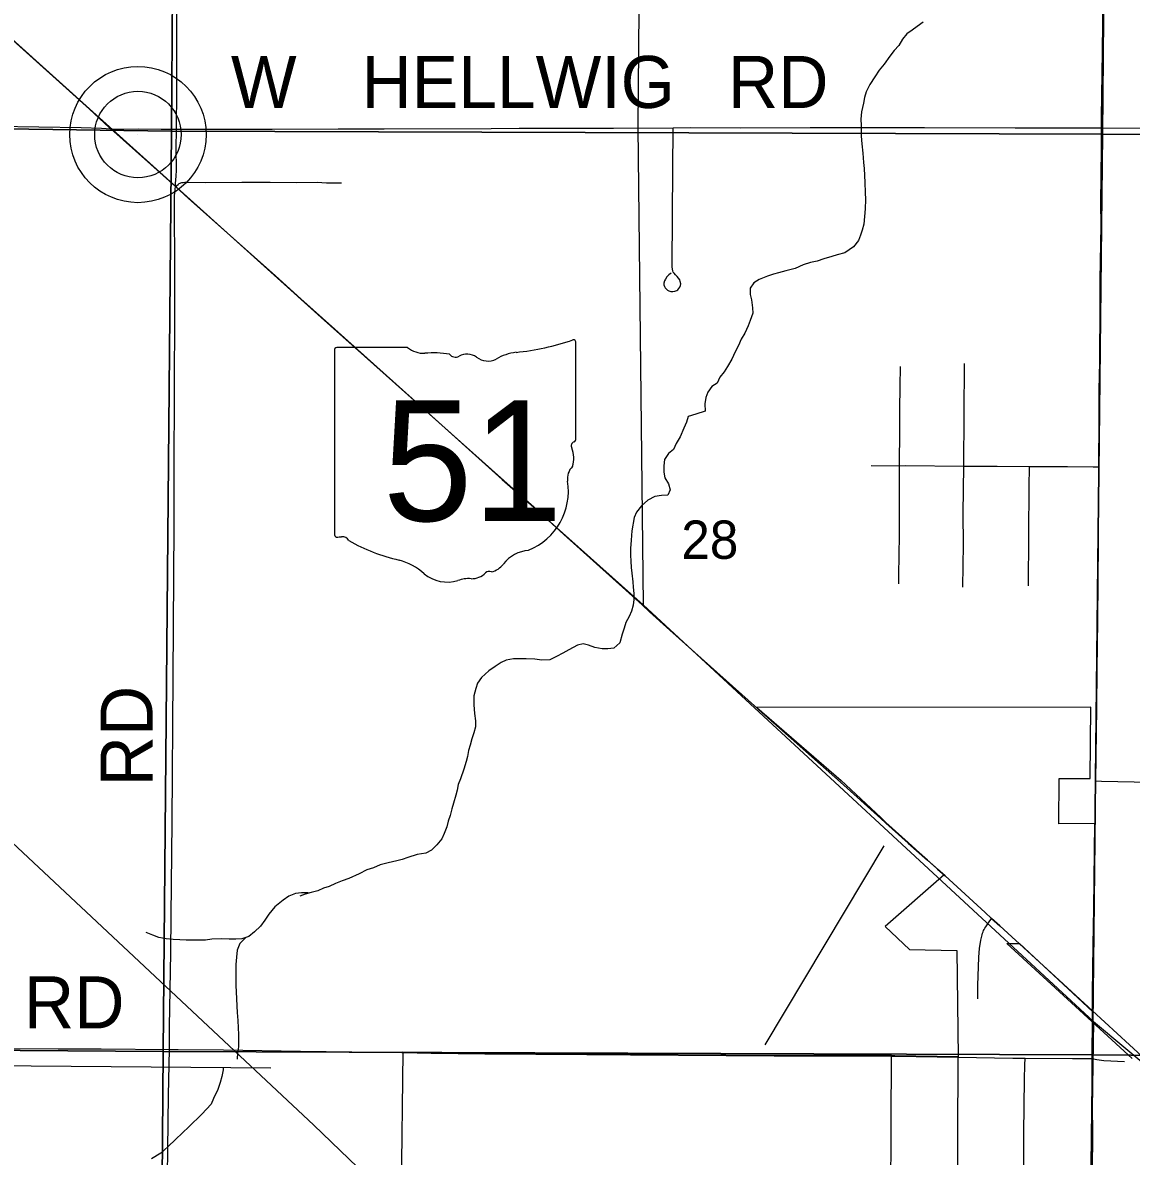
# Model space of a CAD drawing. Extents: x 0 to 34, y 0 to 22.
# Drawn here: x 6.452 to 7.662, y 15.265 to 16.502 of the extents above; entities that cross this region are included whole.
import ezdxf

# ---------------------------------------------------------------- set-up
doc = ezdxf.new("R2010")
doc.units = 0
for name, color, linetype in [('Default', 7, 'Continuous'), ('GM_X_City_Street', 7, 'Continuous'), ('GM_X_County_Road', 7, 'Continuous'), ('GM_X_Minor_River', 7, 'Continuous'), ('GM_X_Rail_Line', 7, 'Continuous'), ('GM_X_Section', 7, 'Continuous'), ('GM_X_Section_Text', 7, 'Continuous'), ('GM_X_State_Location', 7, 'Continuous'), ('GM_X_State_Route', 7, 'Continuous'), ('GM_X_State_Shield', 7, 'Continuous'), ('GM_X_Township_Road', 7, 'Continuous'), ('GM_X_Township_Road_Text', 7, 'Continuous'), ('GM_X_Unincorporated', 7, 'Continuous'), ('GM_X_Unincorporated_Location', 7, 'Continuous')]:
    doc.layers.add(name, color=color, linetype=linetype)

msp = doc.modelspace()

# ---------------------------------------------------------------- linework, layer by layer
at = {"layer": 'Default'}
msp.add_lwpolyline([(7.6625, 15.3715), (7.5256, 15.497), (7.5396, 15.4969), (7.6191, 15.4226), (7.6193, 15.4426), (7.6201, 15.4951), (7.6207, 15.5352), (7.6215, 15.5978), (7.6218, 15.6278), (7.5824, 15.6274), (7.583, 15.6771), (7.6166, 15.6769), (7.6174, 15.7548), (7.2529, 15.7546), (7.3449, 15.6747), (7.3881, 15.6343), (7.3937, 15.629), (7.3936, 15.6289), (7.4179, 15.607), (7.4388, 15.5883), (7.4573, 15.5719), (7.3929, 15.5155), (7.4195, 15.4902), (7.4713, 15.4893), (7.4725, 15.3733), (7.4036, 15.3744), (7.3998, 15.3745), (7.362, 15.3746), (7.2715, 15.3747), (7.1147, 15.3757), (7.067, 15.3762), (6.9559, 15.3769), (6.897, 15.3779), (6.8663, 15.3783), (6.8645, 15.2275)], dxfattribs=at)
at = {"layer": 'GM_X_City_Street'}
for points in [[(7.4941, 15.4366), (7.4942, 15.4509), (7.4951, 15.4821), (7.4959, 15.4914), (7.4973, 15.5005), (7.4987, 15.5065), (7.4992, 15.5081), (7.4998, 15.5098), (7.5003, 15.511), (7.5008, 15.5121), (7.5017, 15.5135), (7.5027, 15.5152), (7.5056, 15.5193), (7.509, 15.5243)], [(7.3978, 15.1171), (7.3978, 15.119), (7.3979, 15.1731), (7.3983, 15.2203), (7.3993, 15.2661), (7.3995, 15.3037), (7.4, 15.3716), (7.4, 15.3739)], [(7.4703, 15.1166), (7.4714, 15.1932), (7.4721, 15.2501), (7.4724, 15.2871), (7.4727, 15.3698), (7.4727, 15.3728)], [(7.4727, 15.3728), (7.5322, 15.3718), (7.5456, 15.3717), (7.5974, 15.3712), (7.6188, 15.3712)], [(7.542, 14.9047), (7.5419, 14.9076), (7.5416, 14.9133), (7.5417, 14.9334), (7.5421, 14.9939), (7.5423, 15.0326), (7.5429, 15.0915), (7.5431, 15.1101), (7.5433, 15.1165), (7.5436, 15.1287), (7.5438, 15.1875), (7.5437, 15.203), (7.5442, 15.2495), (7.5442, 15.2501), (7.5442, 15.265), (7.5443, 15.2898), (7.5449, 15.3486), (7.5454, 15.3641), (7.5456, 15.3717)], [(7.6188, 15.3712), (7.6239, 15.3702), (7.6317, 15.3692), (7.6541, 15.368)]]:
    msp.add_lwpolyline(points, dxfattribs=at)
at = {"layer": 'GM_X_County_Road'}
for p, q in [((7.6227, 15.6745), (7.6239, 15.7541)), ((7.622, 15.6272), (7.6227, 15.6745)), ((7.6192, 15.4095), (7.6193, 15.4233))]:
    msp.add_line(p, q, dxfattribs=at)
for points in [[(7.6291, 16.3875), (7.6291, 16.399), (7.63, 16.4704), (7.6314, 16.5977), (7.6327, 16.694), (7.6332, 16.7499), (7.6341, 16.8182), (7.6347, 16.8648), (7.6351, 16.9176), (7.6358, 16.9672), (7.6359, 16.9859), (7.6362, 17.0194)], [(7.6263, 16.0175), (7.6265, 16.0698), (7.6266, 16.1009), (7.6271, 16.1319), (7.6275, 16.194), (7.6277, 16.222), (7.6285, 16.281), (7.6284, 16.3058), (7.629, 16.3648), (7.6291, 16.3875)], [(7.6239, 15.7541), (7.6242, 15.7956), (7.625, 15.85), (7.6256, 15.935), (7.6263, 16.0175)], [(7.6193, 15.4233), (7.6196, 15.442), (7.6203, 15.4945), (7.6209, 15.5347), (7.6217, 15.5972), (7.622, 15.6272)], [(7.6188, 15.3712), (7.6189, 15.3828), (7.6192, 15.4056), (7.6192, 15.4095)], [(7.6191, 15.2489), (7.6196, 15.2882), (7.6187, 15.3518), (7.6188, 15.3712)]]:
    msp.add_lwpolyline(points, dxfattribs=at)
at = {"layer": 'GM_X_Minor_River'}
for points in [[(7.4344, 16.5029), (7.4279, 16.498), (7.4222, 16.4942), (7.4165, 16.49), (7.412, 16.4843), (7.4078, 16.4775), (7.4029, 16.4718), (7.398, 16.4657), (7.3919, 16.457), (7.3862, 16.4505), (7.3817, 16.4433), (7.3763, 16.435), (7.3722, 16.427), (7.3703, 16.4205), (7.3691, 16.4145), (7.3672, 16.405), (7.3665, 16.397), (7.3668, 16.3902), (7.3668, 16.3784), (7.3676, 16.37), (7.3684, 16.3598), (7.3691, 16.3495), (7.3699, 16.3431), (7.3706, 16.3279), (7.371, 16.3169), (7.3714, 16.3093), (7.371, 16.299), (7.3695, 16.2823), (7.3679, 16.2759), (7.3661, 16.2702), (7.3638, 16.2645), (7.3585, 16.2576), (7.349, 16.2512), (7.3406, 16.2489), (7.3346, 16.247), (7.3259, 16.2444), (7.3187, 16.2421), (7.3115, 16.2406), (7.3035, 16.2379), (7.2948, 16.2338), (7.2845, 16.2315), (7.2766, 16.2292), (7.2709, 16.2277), (7.2644, 16.2254), (7.2553, 16.222), (7.2497, 16.2182), (7.2455, 16.2125), (7.2455, 16.2057), (7.247, 16.1996), (7.2481, 16.1909), (7.2485, 16.1852), (7.2455, 16.1772), (7.2432, 16.1715), (7.2398, 16.1632), (7.2356, 16.1567), (7.233, 16.1499), (7.2292, 16.143), (7.2254, 16.1351)], [(7.2254, 16.1351), (7.2208, 16.1271), (7.217, 16.121), (7.2125, 16.1153), (7.2094, 16.1089), (7.2038, 16.1051), (7.1992, 16.099), (7.1973, 16.0929), (7.1962, 16.0861), (7.1965, 16.0781), (7.1863, 16.0747), (7.178, 16.0724), (7.1761, 16.066), (7.173, 16.0595), (7.1692, 16.05), (7.1647, 16.0428), (7.162, 16.0364), (7.1563, 16.0318), (7.1522, 16.0254), (7.1514, 16.0185), (7.1514, 16.0117), (7.1525, 16.0053), (7.1563, 15.9988), (7.1582, 15.9923), (7.1556, 15.9866), (7.1487, 15.9859), (7.1415, 15.9848), (7.134, 15.981), (7.1271, 15.9749), (7.1214, 15.9677), (7.1188, 15.962), (7.1165, 15.9476), (7.1158, 15.9373), (7.115, 15.9282), (7.115, 15.921), (7.1154, 15.9145), (7.1157, 15.9073), (7.1165, 15.9012), (7.1176, 15.8917), (7.118, 15.886), (7.1184, 15.8792), (7.1184, 15.8724), (7.118, 15.8663), (7.1161, 15.8598), (7.1134, 15.8538), (7.11, 15.8473), (7.1081, 15.8412), (7.1059, 15.8348), (7.1032, 15.8253), (7.0968, 15.8192), (7.0903, 15.8185), (7.0839, 15.8185), (7.0759, 15.82), (7.0691, 15.8227), (7.0634, 15.8242), (7.057, 15.8227), (7.0475, 15.8174), (7.041, 15.814), (7.0342, 15.8102), (7.027, 15.8067), (7.0183, 15.8064), (7.0107, 15.8075), (7.0012, 15.8079), (6.9872, 15.8079), (6.9792, 15.8064), (6.9736, 15.8037), (6.9671, 15.7992), (6.9603, 15.7946), (6.9523, 15.7874), (6.9481, 15.781), (6.9462, 15.7753), (6.944, 15.7673), (6.944, 15.7574), (6.9447, 15.7479), (6.9459, 15.74), (6.9459, 15.7335), (6.944, 15.7271), (6.9417, 15.7202), (6.9398, 15.7134), (6.9383, 15.7077), (6.9371, 15.7012), (6.9356, 15.6956), (6.9329, 15.6872), (6.9295, 15.6766), (6.9269, 15.6705), (6.9257, 15.6644), (6.9242, 15.6587), (6.9219, 15.65), (6.92, 15.6439), (6.9181, 15.6367), (6.9159, 15.6306), (6.9144, 15.6242), (6.9117, 15.617), (6.909, 15.6113), (6.9037, 15.6048), (6.8977, 15.5988), (6.8916, 15.5957), (6.8821, 15.5942), (6.8719, 15.5908), (6.8658, 15.5885), (6.8598, 15.587)], [(7.3916, 15.6037), (7.2615, 15.3863)], [(6.8598, 15.587), (6.8503, 15.5851), (6.8416, 15.5828), (6.8344, 15.5794), (6.8271, 15.5772), (6.8188, 15.573), (6.8074, 15.5677), (6.8002, 15.5654), (6.793, 15.5624), (6.7862, 15.5593), (6.7798, 15.5574), (6.7737, 15.5544), (6.7665, 15.5525), (6.76, 15.5506), (6.754, 15.5487)], [(6.7631, 15.5521), (6.7559, 15.5521), (6.7494, 15.5514), (6.7422, 15.5484), (6.7358, 15.5442), (6.7267, 15.537), (6.7202, 15.529), (6.7157, 15.5222), (6.7111, 15.5157), (6.7047, 15.5097), (6.6982, 15.5047), (6.6907, 15.5021), (6.6842, 15.5017), (6.677, 15.5017), (6.6683, 15.5021), (6.6581, 15.5017), (6.6509, 15.5006), (6.63, 15.5006), (6.6232, 15.501), (6.6156, 15.5014), (6.608, 15.5021), (6.6001, 15.5036), (6.5936, 15.5059), (6.5864, 15.509)], [(6.695, 15.5036), (6.6884, 15.4968), (6.6857, 15.4895), (6.685, 15.4819), (6.6842, 15.474), (6.6842, 15.4512), (6.6849, 15.4368), (6.6853, 15.4284), (6.6857, 15.4216), (6.6865, 15.4128), (6.6868, 15.4049), (6.6872, 15.3977), (6.6872, 15.384), (6.6861, 15.3775), (6.6857, 15.3707)], [(6.7224, 15.3608), (5.1099, 15.3744), (5.1125, 15.1557), (4.6992, 15.1313)], [(6.6705, 15.3612), (6.6705, 15.3589), (6.669, 15.3517), (6.6671, 15.3453), (6.6644, 15.3373), (6.6599, 15.3278), (6.6572, 15.3214), (6.647, 15.3107), (6.633, 15.2967), (6.6261, 15.2902), (6.6182, 15.283), (6.6102, 15.2751), (6.6022, 15.2679), (6.592, 15.2618)]]:
    msp.add_lwpolyline(points, dxfattribs=at)
at = {"layer": 'GM_X_Rail_Line'}
msp.add_line((7.1287, 15.8668), (7.6203, 15.4116), dxfattribs=at)
for points in [[(5.1871, 17.6191), (5.4266, 17.4037), (5.6472, 17.1998), (6.051, 16.8348), (6.7774, 16.1806), (7.1287, 15.8668)], [(7.1325, 17.6042), (7.1272, 17.4005), (7.1287, 17.0765), (7.1229, 16.3878), (7.1287, 15.8668)], [(4.6999, 17.2234), (5.1959, 16.7623), (5.6141, 16.3779), (6.1219, 15.9048), (6.7692, 15.2987), (7.1796, 14.9035), (7.6056, 14.5217)], [(7.6203, 15.4116), (7.6101, 14.7476), (7.6056, 14.5217)], [(7.6203, 15.4116), (7.6888, 15.3547), (7.6772, 14.5433), (7.683, 14.4528), (7.7895, 14.3507), (8.3611, 14.3552), (8.75, 14.3552), (8.9, 14.2113)]]:
    msp.add_lwpolyline(points, dxfattribs=at)
at = {"layer": 'GM_X_Section'}
for points in [[(6.6213, 17.4032), (6.6138, 16.3837), (5.6285, 16.3977), (5.6487, 17.4026)], [(7.639, 17.3962), (7.6303, 16.3805), (6.6138, 16.3837), (6.6213, 17.4032)], [(7.639, 17.3962), (8.6426, 17.3907), (8.6324, 16.375), (7.6303, 16.3805)], [(5.6285, 16.3977), (6.6138, 16.3837), (6.6049, 15.379), (5.6172, 15.3858)], [(7.6303, 16.3805), (7.6191, 15.3755), (6.6049, 15.379), (6.6138, 16.3837)], [(7.6303, 16.3805), (8.6324, 16.375), (8.6234, 15.3665), (7.6191, 15.3755)], [(6.5967, 14.3417), (5.5962, 14.3464), (5.6172, 15.3858), (6.6049, 15.379)], [(7.6191, 15.3755), (7.6069, 14.3511), (6.5967, 14.3417), (6.6049, 15.379)], [(8.6234, 15.3665), (8.6163, 14.3591), (7.6069, 14.3511), (7.6191, 15.3755)]]:
    msp.add_lwpolyline(points, close=True, dxfattribs=at)
at = {"layer": 'GM_X_State_Route'}
for p, q in [((7.3223, 15.6923), (7.255, 15.7522)), ((7.255, 15.7522), (7.3223, 15.6923)), ((7.6193, 15.4233), (7.5827, 15.4569)), ((7.5827, 15.4569), (7.6193, 15.4233))]:
    msp.add_line(p, q, dxfattribs=at)
for points in [[(6.5476, 16.3865), (6.5464, 16.3876), (6.5244, 16.4079), (6.4411, 16.4827)], [(6.4411, 16.4827), (6.5244, 16.4079), (6.5464, 16.3876), (6.5476, 16.3865)], [(7.1357, 15.8592), (7.1276, 15.8666), (7.0422, 15.9436), (7.0122, 15.9706), (6.9749, 16.0036), (6.8871, 16.0826), (6.7921, 16.1676), (6.755, 16.2008), (6.7274, 16.2258), (6.6323, 16.3107), (6.6182, 16.3234), (6.5476, 16.3865)], [(6.5476, 16.3865), (6.6182, 16.3234), (6.6323, 16.3107), (6.7274, 16.2258), (6.755, 16.2008), (6.7921, 16.1676), (6.8871, 16.0826), (6.9749, 16.0036), (7.0122, 15.9706), (7.0422, 15.9436), (7.1276, 15.8666), (7.1357, 15.8592)], [(7.255, 15.7522), (7.2535, 15.7536), (7.158, 15.8391), (7.1357, 15.8592)], [(7.1357, 15.8592), (7.158, 15.8391), (7.2535, 15.7536), (7.255, 15.7522)], [(7.4492, 15.5787), (7.439, 15.5878), (7.4181, 15.6064), (7.3938, 15.6283), (7.388, 15.6335), (7.344, 15.673), (7.3223, 15.6923)], [(7.3223, 15.6923), (7.344, 15.673), (7.388, 15.6335), (7.3938, 15.6283), (7.4181, 15.6064), (7.439, 15.5878), (7.4492, 15.5787)], [(7.5827, 15.4569), (7.5179, 15.5163), (7.509, 15.5243), (7.5021, 15.5306), (7.4583, 15.5706), (7.4499, 15.5781), (7.4492, 15.5787)], [(7.4492, 15.5787), (7.4499, 15.5781), (7.4583, 15.5706), (7.5021, 15.5306), (7.509, 15.5243), (7.5179, 15.5163), (7.5827, 15.4569)], [(7.9423, 15.1241), (7.9401, 15.126), (7.8926, 15.1691), (7.8474, 15.2116), (7.8268, 15.2306), (7.7928, 15.2623), (7.6912, 15.3569), (7.6806, 15.3666), (7.673, 15.3737), (7.6193, 15.4233)], [(7.6193, 15.4233), (7.673, 15.3737), (7.6806, 15.3666), (7.6912, 15.3569), (7.7928, 15.2623), (7.8268, 15.2306), (7.8474, 15.2116), (7.8926, 15.1691), (7.9401, 15.126), (7.9423, 15.1241)]]:
    msp.add_lwpolyline(points, dxfattribs=at)
at = {"layer": 'GM_X_State_Shield'}
for p, q in [((6.7918, 16.1443), (6.7918, 15.9441)), ((6.8716, 16.1477), (6.7944, 16.1477)), ((7.0554, 16.048), (7.0554, 16.1527)), ((7.0554, 16.048), (7.0554, 16.048))]:
    msp.add_line(p, q, dxfattribs=at)
for centre, radius, start, end in [((6.9615, 16.4205), 0.2796, 275.8445, 288.9065), ((7.0525, 16.1531), 0.00294, 351.8621, 97.738), ((6.7948, 16.1447), 0.00305, 98.1301, 188.1301), ((6.89, 16.1709), 0.0296, 231.6195, 271.1119), ((6.8998, 16.0354), 0.1064, 80.4867, 94.9883), ((6.9972, 16.0866), 0.0563, 97.3462, 120.7689), ((6.9239, 16.1457), 0.00855, 219.7921, 297.1024), ((6.9365, 16.1226), 0.0178, 54.4667, 119.1411), ((6.9594, 16.1543), 0.0214, 233.8562, 294.8282), ((7.0547, 16.0403), 0.00454, 107.944, 210.337), ((7.0523, 16.0476), 0.00314, 289.6038, 7.7341), ((7.0258, 16.0271), 0.0273, 340.033, 23.6496), ((7.0659, 16.0042), 0.0198, 136.8065, 186.9296), ((6.9772, 15.9909), 0.0699, 292.3089, 8.9858), ((6.7948, 15.9437), 0.00308, 171.9584, 258.3066), ((6.7953, 15.9642), 0.0235, 267.339, 280.6039), ((6.8001, 15.9326), 0.00848, 29.7484, 93.2717), ((6.9071, 16.1124), 0.2019, 240.4129, 257.1985), ((7.0067, 15.888), 0.0383, 94.4031, 142.5768), ((6.8469, 15.8542), 0.0632, 47.1842, 75.836), ((6.9581, 15.9247), 0.0226, 282.8732, 323.2771), ((6.9153, 15.9316), 0.0401, 230.7004, 286.2918), ((6.9384, 15.8624), 0.0329, 85.6951, 111.2099), ((6.9414, 15.9166), 0.0214, 268.777, 315.5493), ((6.9607, 15.8972), 0.00601, 65.7517, 132.6484)]:
    msp.add_arc(centre, radius, start, end, dxfattribs=at)
at = {"layer": 'GM_X_Township_Road'}
for p, q in [((7.4789, 16.0181), (7.4794, 16.1301)), ((7.3776, 16.0188), (7.4086, 16.0186))]:
    msp.add_line(p, q, dxfattribs=at)
for points in [[(6.6194, 16.3862), (6.6199, 16.4282), (6.6199, 16.4904), (6.62, 16.5619), (6.6203, 16.6349)], [(6.4141, 16.3893), (6.4227, 16.3892), (6.5155, 16.3878), (6.5375, 16.387), (6.5476, 16.3865)], [(6.5476, 16.3865), (6.5567, 16.3862), (6.5777, 16.3863), (6.6028, 16.3862), (6.6194, 16.3862)], [(6.6182, 16.3234), (6.6184, 16.3267), (6.6191, 16.3349), (6.6194, 16.3413), (6.6192, 16.3661), (6.6194, 16.3848), (6.6194, 16.3862)], [(6.6194, 16.3862), (6.6523, 16.386), (6.6927, 16.386), (6.7237, 16.3862), (6.7957, 16.3864), (6.8459, 16.3866), (6.963, 16.3867), (6.9935, 16.387), (7.0626, 16.3872), (7.0965, 16.3873), (7.1614, 16.3876)], [(7.1594, 16.229), (7.1567, 16.2269), (7.1547, 16.2248), (7.1531, 16.2224), (7.1521, 16.2203), (7.1515, 16.218), (7.1515, 16.2161), (7.152, 16.2143), (7.1527, 16.2129), (7.1538, 16.2116), (7.1553, 16.2104), (7.1569, 16.2094), (7.1589, 16.2089), (7.1611, 16.2088), (7.1633, 16.2091), (7.1654, 16.2099), (7.1666, 16.2108), (7.1678, 16.212), (7.1689, 16.2135), (7.1695, 16.2153), (7.1697, 16.2172), (7.1693, 16.2196), (7.1687, 16.2216), (7.1675, 16.2235), (7.166, 16.2253), (7.1641, 16.2271), (7.1625, 16.2288), (7.1616, 16.23), (7.1611, 16.2314), (7.1606, 16.2352), (7.1606, 16.2385), (7.1606, 16.2459), (7.1607, 16.2819), (7.1613, 16.3521), (7.1615, 16.3772), (7.1614, 16.3859), (7.1614, 16.3876)], [(7.1614, 16.3876), (7.1808, 16.3877), (7.2353, 16.3875), (7.3112, 16.3877), (7.4357, 16.3877), (7.5348, 16.3876), (7.6291, 16.3875)], [(7.6291, 16.3875), (7.7136, 16.387), (7.8109, 16.3859), (7.9047, 16.3847), (8.0794, 16.3818), (8.2166, 16.3802), (8.3186, 16.3793), (8.4335, 16.3779), (8.5236, 16.3771), (8.6342, 16.3763)], [(6.6182, 16.3234), (6.6198, 16.3247), (6.6211, 16.3258), (6.6225, 16.3267), (6.6233, 16.3272), (6.6243, 16.3275), (6.6254, 16.3278), (6.6267, 16.328), (6.6284, 16.3281), (6.6322, 16.3281), (6.6508, 16.3279), (6.6909, 16.3281), (6.7217, 16.3281), (6.7499, 16.3278), (6.773, 16.3281), (6.7831, 16.3276), (6.7994, 16.3274)], [(6.6117, 15.3813), (6.6118, 15.3859), (6.6119, 15.4063), (6.6131, 15.4866), (6.6135, 15.527), (6.6147, 15.6295), (6.6158, 15.7881), (6.6167, 15.9528), (6.6168, 16.0212), (6.6174, 16.0927), (6.6175, 16.1953), (6.6177, 16.2512), (6.6173, 16.2854), (6.6172, 16.3041), (6.6173, 16.3128), (6.6179, 16.3205), (6.6182, 16.3234)], [(7.4086, 16.0186), (7.4089, 16.0582), (7.4089, 16.08), (7.4094, 16.105), (7.4097, 16.1269)], [(7.4077, 15.8896), (7.4079, 15.8992), (7.4085, 15.9428), (7.4084, 15.9584), (7.4085, 15.9834), (7.4086, 16.0186)], [(7.4086, 16.0186), (7.415, 16.0187), (7.4789, 16.0181)], [(7.4777, 15.8858), (7.4784, 15.9326), (7.4782, 15.9665), (7.4789, 16.0181)], [(7.4789, 16.0181), (7.515, 16.018), (7.5505, 16.0179)], [(7.5493, 15.8873), (7.55, 15.9968), (7.5505, 16.0161), (7.5505, 16.0179)], [(7.5505, 16.0179), (7.592, 16.0178), (7.6201, 16.0175), (7.6263, 16.0175)], [(7.6227, 15.6745), (7.629, 15.6743), (7.6826, 15.6729), (7.7022, 15.6726), (7.7048, 15.6726)], [(5.6188, 15.3881), (5.6257, 15.388), (5.6692, 15.3872), (5.7439, 15.387), (5.8807, 15.3852), (5.9989, 15.3842), (6.0425, 15.3837), (6.1296, 15.3829), (6.2851, 15.3824), (6.3442, 15.3823), (6.4344, 15.3821), (6.4904, 15.3817), (6.5371, 15.3817), (6.6117, 15.3813)], [(6.604, 14.6478), (6.6041, 14.666), (6.6064, 14.8743), (6.6075, 15.0732), (6.61, 15.2721), (6.6106, 15.3312), (6.6117, 15.3813)], [(6.6117, 15.3813), (6.6211, 15.3812), (6.6708, 15.3808), (6.7548, 15.3792), (6.8108, 15.3785), (6.8655, 15.3778)], [(6.8655, 15.3778), (6.8665, 15.3778), (6.8972, 15.3773), (6.9561, 15.3763), (7.0673, 15.3756), (7.1149, 15.3752), (7.2717, 15.3742), (7.3622, 15.3741), (7.4, 15.3739)], [(7.4, 15.3739), (7.4038, 15.3739), (7.4727, 15.3728)]]:
    msp.add_lwpolyline(points, dxfattribs=at)
at = {"layer": 'GM_X_Unincorporated'}
for radius in [0.0744, 0.0472]:
    msp.add_circle((6.5773, 16.3802), radius, dxfattribs=at)
at = {"layer": 'GM_X_Unincorporated_Location'}
msp.add_line((6.5773, 16.3802), (6.5773, 16.3802), dxfattribs=at)

# ---------------------------------------------------------------- texts
at = {"layer": 'GM_X_Section_Text'}
msp.add_text('28', height=0.04186, rotation=0, dxfattribs=at).set_placement((7.1704, 15.9169))
at = {"layer": 'GM_X_State_Location'}
for s in ['s', 'r']:
    msp.add_text(s, height=0.000189, dxfattribs=at).set_placement((6.9206, 16.0309))
msp.add_text('51', height=0.000189, rotation=0, dxfattribs=at).set_placement((6.8729, 16.0171))
at = {"layer": 'GM_X_State_Shield'}
msp.add_text('51', height=0.13184, dxfattribs=at).set_placement((6.8445, 15.9583))
at = {"layer": 'GM_X_Township_Road_Text'}
for s, height, rotation, p in [('W', 0.0568, 0, (6.6788, 16.4092)), ('HELLWIG', 0.05682, 0, (6.8213, 16.4092)), ('RD', 0.05682, 0, (7.2213, 16.4092)), ('RD', 0.05682, 90, (6.5933, 15.6685)), ('RD', 0.05682, 0, (6.4529, 15.4042))]:
    msp.add_text(s, height=height, rotation=rotation, dxfattribs=at).set_placement(p)

doc.saveas('drawing.dxf')
